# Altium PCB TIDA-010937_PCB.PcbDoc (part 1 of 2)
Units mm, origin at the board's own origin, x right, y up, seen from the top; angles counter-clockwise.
Board outline 43.5 x 86.34 mm, 4 copper layers (Top Layer, GND, PWR, Bottom Layer), stack 1.856 mm thick; 90 components, 44 nets, 203 pads, 101 vias.
Unrouted connection lines stored in the file: 1.
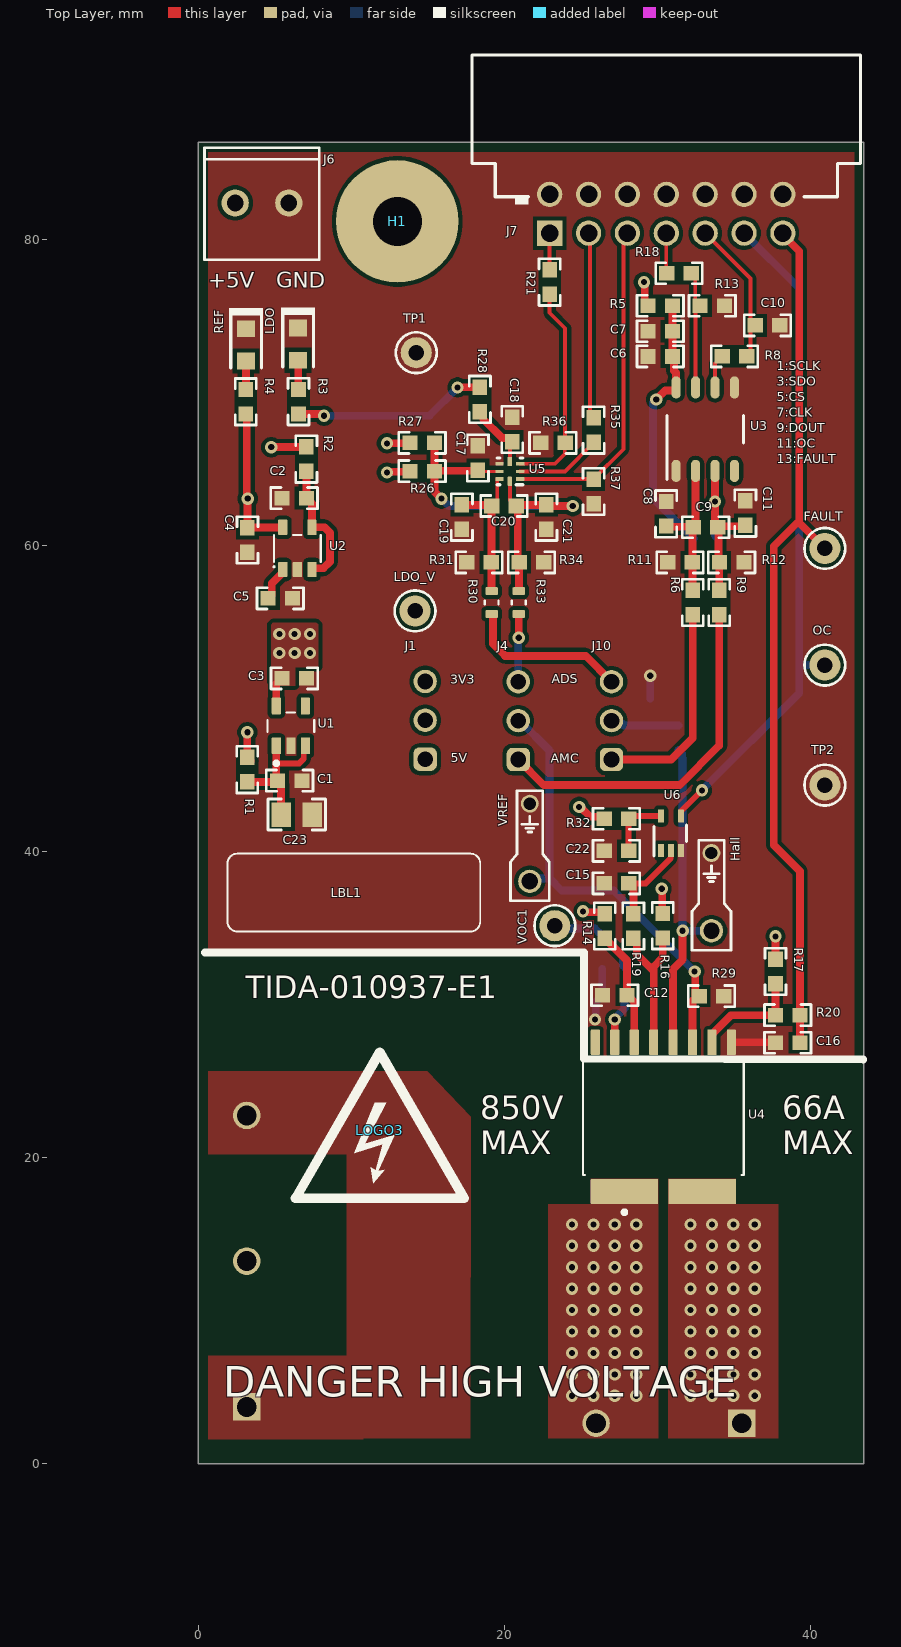
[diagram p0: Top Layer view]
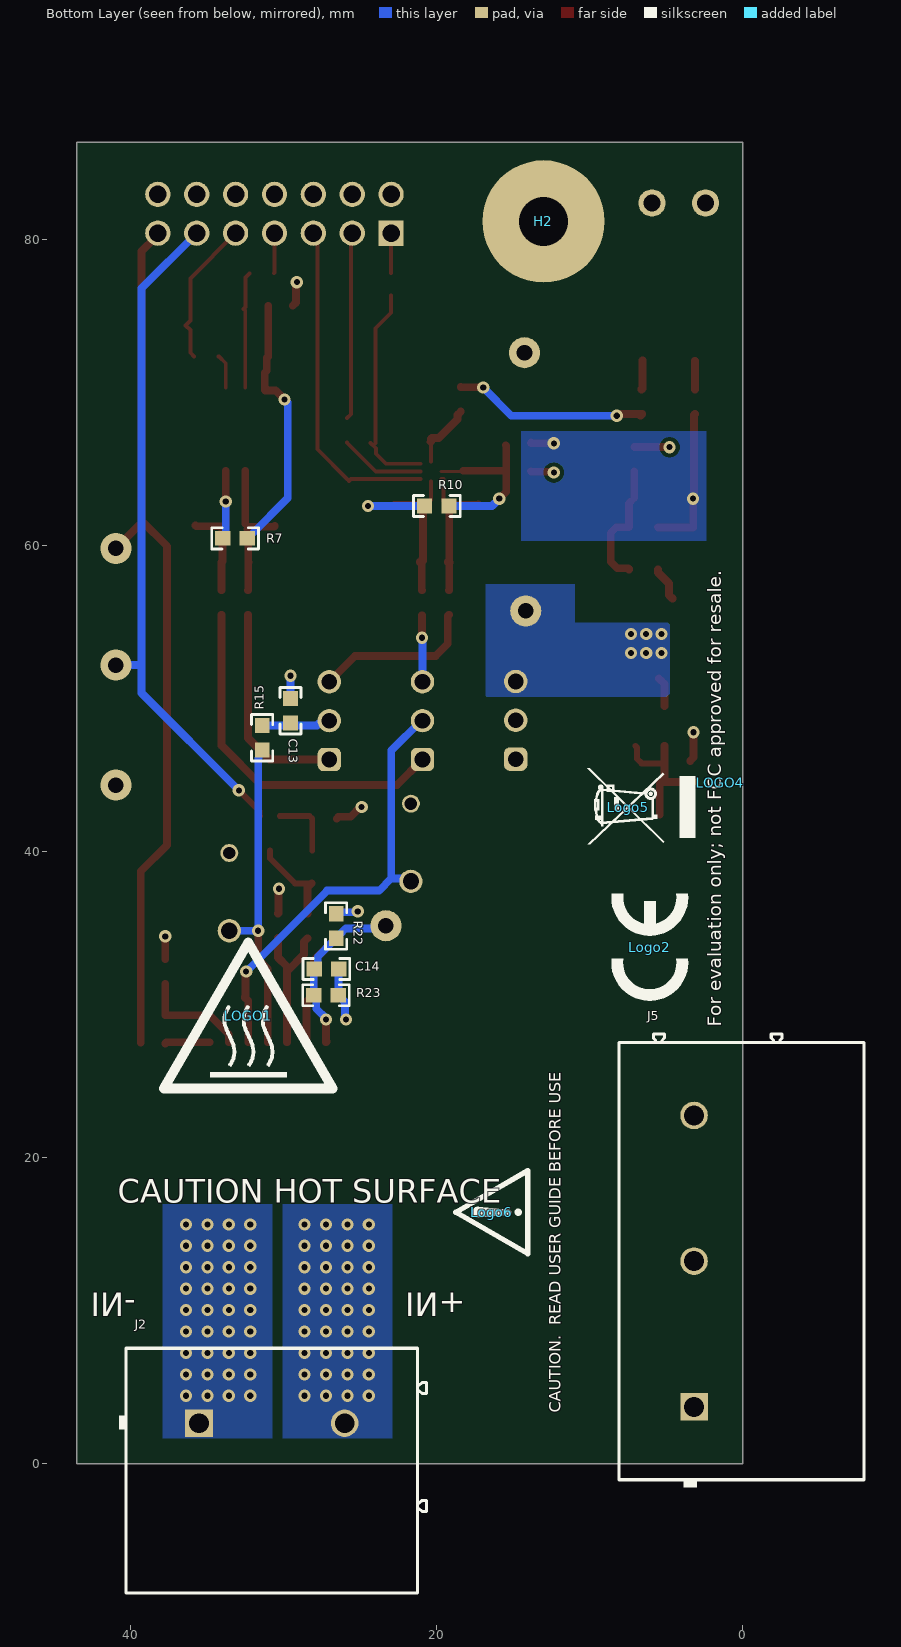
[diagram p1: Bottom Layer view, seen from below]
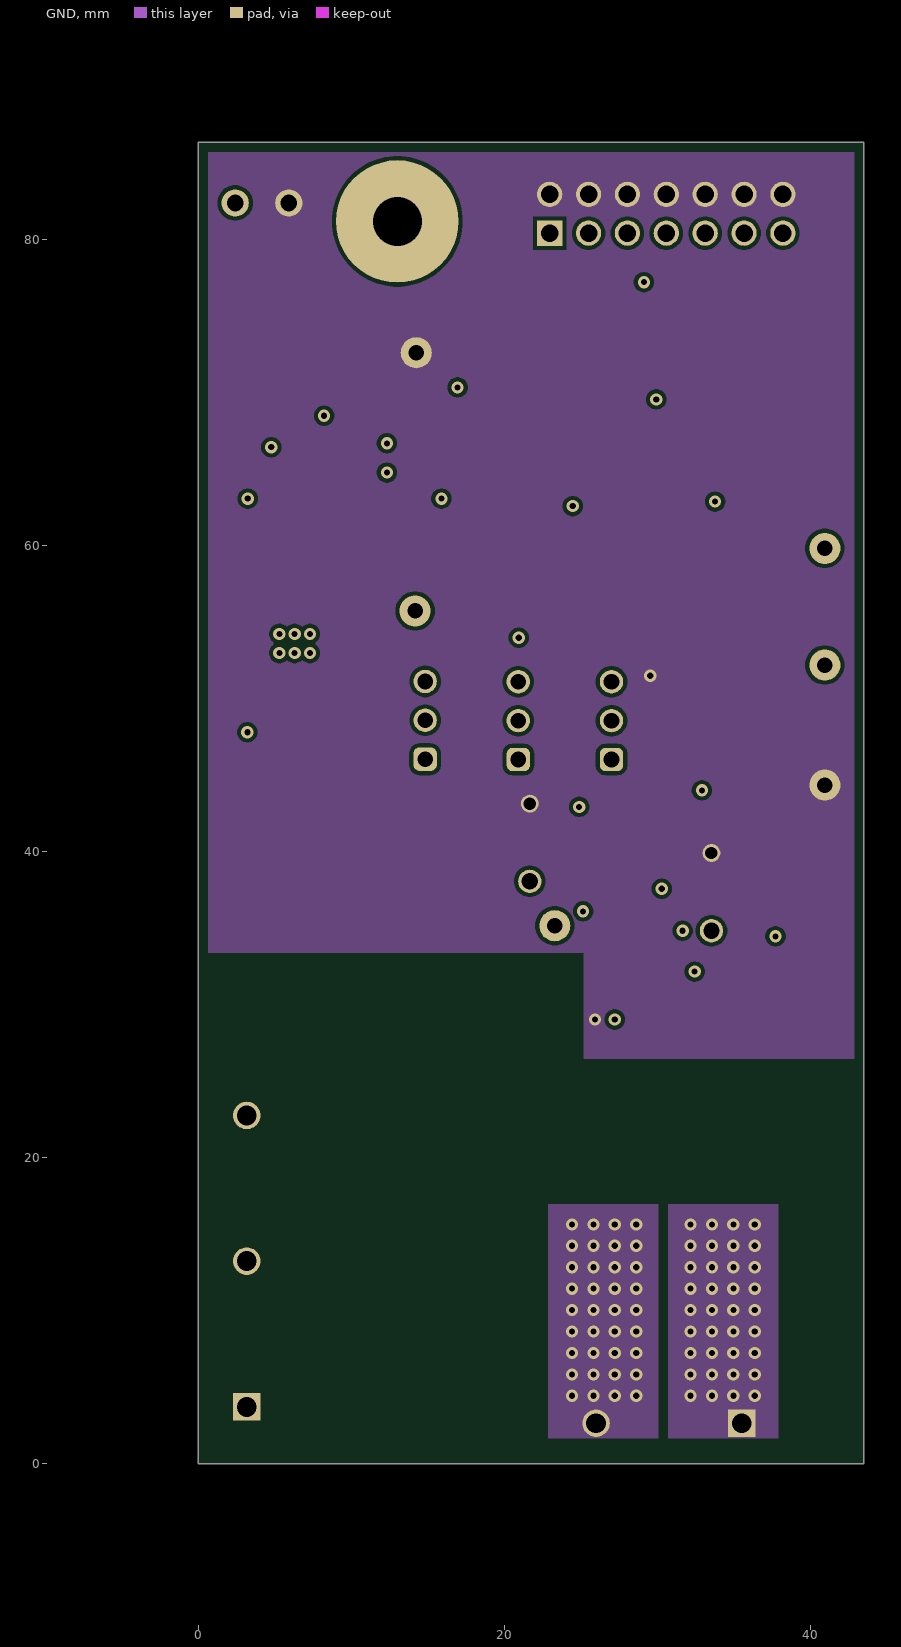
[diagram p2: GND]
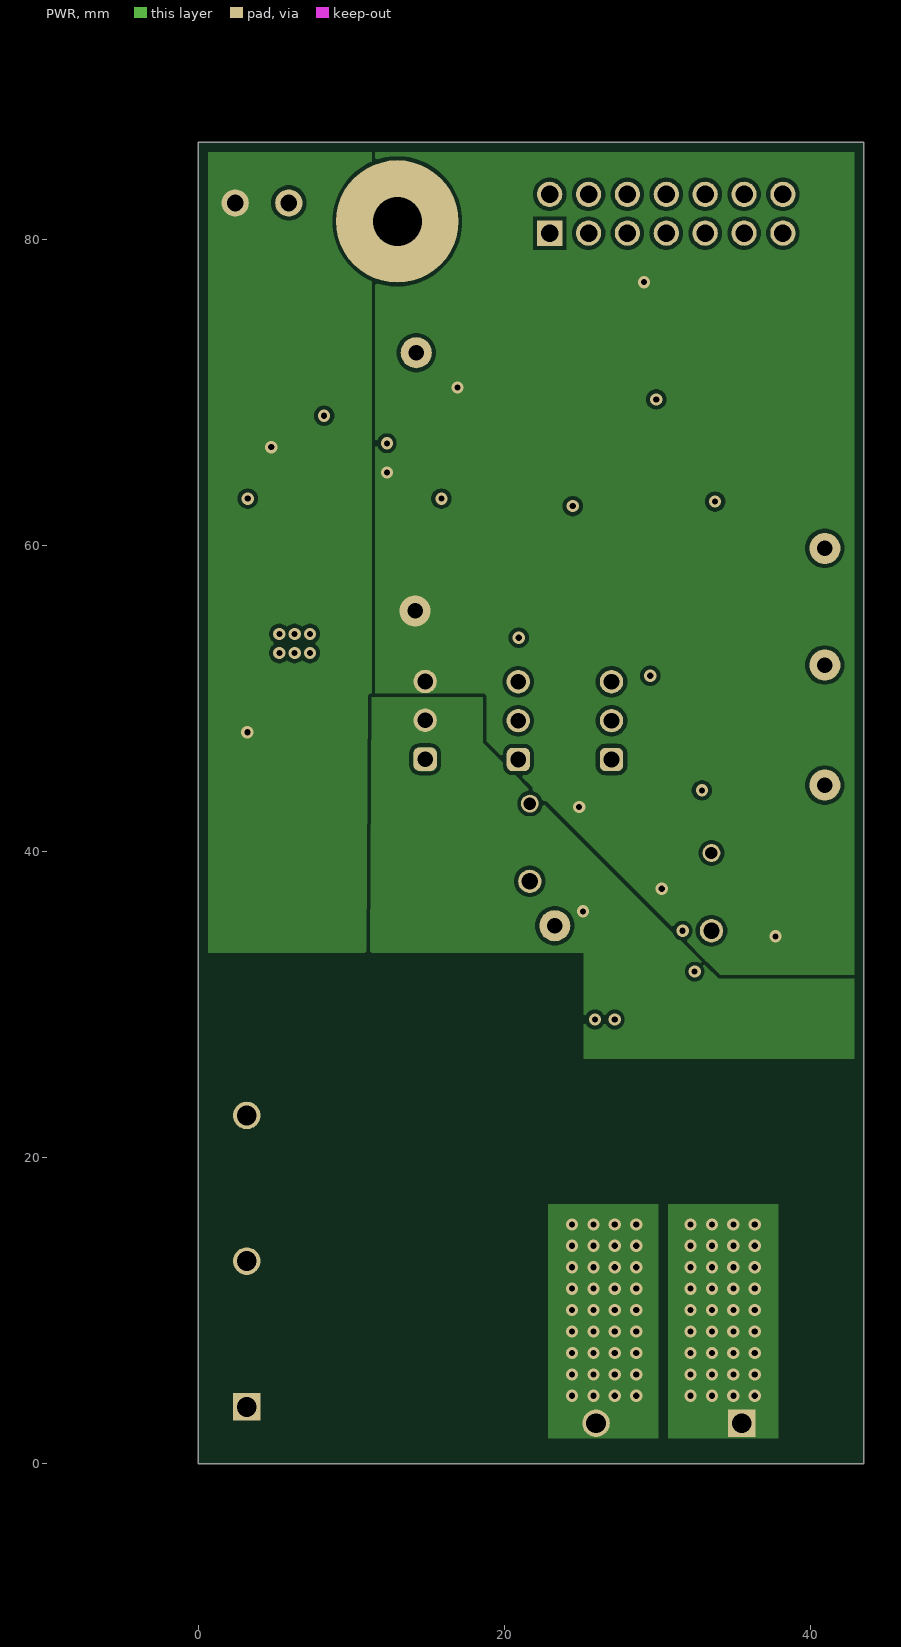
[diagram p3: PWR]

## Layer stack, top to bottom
Top Solder: solder mask 0.0102, Solder Resist, Dk 3.5
Top Layer: signal copper 0.07
Dielectric 1: prepreg 0.0711, PP-006, Dk 4.1
GND: signal copper 0.035
Dielectric1: core 1.5037, FR-4 High Tg, Dk 4.8
PWR: signal copper 0.035
Dielectric 2: prepreg 0.0711, PP-006, Dk 4.1
Bottom Layer: signal copper 0.07
Bottom Solder: solder mask 0.0102, Solder Resist, Dk 3.5

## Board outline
0,0 43.5,0 43.5,86.341 0,86.341

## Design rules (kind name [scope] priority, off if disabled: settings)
AcuteAngle [All] p1: minimum=4.50000000000000E+0001 checktracksonly=FALSE
AssemblyTestPointUsage [All] p1: valid=2
BoardOutlineClearance BoardOutlineClearance_MountingHoles [OnCopper and InComponentClass('Mounting Holes')] p1: gap=1 ignorepadtopadclearanceinfootprint=FALSE
BoardOutlineClearance BoardOutlineClearance_Poly [OnCopper and IsPoly] p2: gap=0.635 ignorepadtopadclearanceinfootprint=FALSE
BoardOutlineClearance [OnCopper and Not InComponentClass('Logo') and not InComponentClass('FiducialMark') and not InRegion(1000,500,4000,800) and not InPoly] p3: gap=1.016 ignorepadtopadclearanceinfootprint=FALSE
Clearance Clearance_Keepouts [((IsTrack Or IsArc) And Not InPoly) And IsFree and IsKeepOut vs ((IsTrack Or IsArc) And Not InPoly) And IsFree and IsKeepOut] p1: gap=0 ignorepadtopadclearanceinfootprint=FALSE
Clearance Clearance_Poly [InPolygon] p2: gap=0.254 ignorepadtopadclearanceinfootprint=TRUE
Clearance Clearance_FiducialMark [IsKeepOut and InComponentClass('FiducialMark') vs IsPad and InComponentClass('FiducialMark')] p3: gap=0 ignorepadtopadclearanceinfootprint=FALSE
Clearance [All] p4: gap=0.2 ignorepadtopadclearanceinfootprint=TRUE except(0: Arc-Arc Arc-Track Track-Track)
ComponentClearance ComponentClearance_MountingHoles_FiducialMarks [InComponentClass('Mounting Holes') vs InComponentClass('FiducialMark')] p1 off: gap=1.27 collisioncheckmode=3 verticalgap=0.254 showdistances=FALSE
ComponentClearance ComponentClearance_Shunt [InComponentClass('Header') vs InComponentClass('Shunt')] p2 off: gap=0 collisioncheckmode=3 verticalgap=0 showdistances=FALSE
ComponentClearance ComponentClearance_Logo [InComponentClass('Logo')] p3 off: gap=0 collisioncheckmode=3 verticalgap=0.254 showdistances=FALSE
ComponentClearance ComponentClearance_ScrewToNut [(HasFootprint('NY PMS 440 0025 PH')) vs (HasFootprint('Keystone_1902C'))] p4 off: gap=0.127 collisioncheckmode=3 verticalgap=0.254 showdistances=FALSE
ComponentClearance ComponentClearance_MountingHoles [InComponentClass('Mounting Holes')] p5 off: gap=2.54 collisioncheckmode=3 verticalgap=2540 showdistances=FALSE
ComponentClearance ComponentClearance_SmallPassives [HasFootprint('0201*') or HasFootprint('0402*') or HasFootprint('0508') or HasFootprint('0603*') or HasFootprint('0612') or HasFootprint('0805*') or HasFootprint('0815*') or HasFootprint('0830*') or HasFootprint('1206*') or HasFootprint('1210*') or HasFootprint('1808*') or HasFootprint('1812*') or HasFootprint('1825*') or HasFootprint('2010*') or HasFootprint('2220*') or HasFootprint('2225*') or HasFootprint('2512*') or HasFootprint('2728*') or HasFootprint('3518*') vs HasFootprint('0201*') or HasFootprint('0402*') or HasFootprint('0508') or HasFootprint('0603*') or HasFootprint('0612') or HasFootprint('0805*') or HasFootprint('0815*') or HasFootprint('0830*') or HasFootprint('1206*') or HasFootprint('1210*') or HasFootprint('1808*') or HasFootprint('1812*') or HasFootprint('1825*') or HasFootprint('2010*') or HasFootprint('2220*') or HasFootprint('2225*') or HasFootprint('2512*') or HasFootprint('2728*') or HasFootprint('3518*')] p6 off: gap=0.38 collisioncheckmode=3 verticalgap=0.254 showdistances=FALSE
ComponentClearance ComponentClearance_THtoSMT [IsThruComponent vs IsSMTComponent] p7 off: gap=0 collisioncheckmode=3 verticalgap=0 showdistances=FALSE
ComponentClearance ComponentClearance_THtoTH [IsThruComponent vs IsThruComponent] p8 off: gap=0.508 collisioncheckmode=3 verticalgap=0 showdistances=FALSE
ComponentClearance [All] p9 off: gap=0 collisioncheckmode=3 verticalgap=0 showdistances=FALSE
DiffPairsRouting [All] p1: maxlimit=2.54 minlimit=0.254 mostfreqgap=0.254 toplayer_minwidth=0.381 toplayer_maxwidth=0.381 toplayer_prefwidth=0.381 midlayer1_minwidth=0.381 midlayer1_maxwidth=0.381 midlayer1_prefwidth=0.381 midlayer2_minwidth=0.381 midlayer2_maxwidth=0.381 midlayer2_prefwidth=0.381 bottomlayer_minwidth=0.381 bottomlayer_maxwidth=0.381 bottomlayer_prefwidth=0.381 maxuncoupledlength=25.4
FabricationTestPointUsage TestPointUsage [All] p1: valid=2 allowmultiple=FALSE
FabricationTestpoint Testpoint [All] p1: side=3 testpointundercomponent=TRUE minsize=1.016 maxsize=2.54 preferedsize=1.524 minholesize=0 maxholesize=1.016 preferedholesize=0.813 testpointgrid=0.025 allowsidetop=TRUE allowsidebottom=TRUE usegrid=TRUE gridtolerance=0
FanoutControl Fanout_LCC [IsLCC] p1: bgadir=Out bgaviamode=Centered fanoutstyle=Auto fanoutdirection=Alternating viagrid=0.025 // Fanout_LCC (Default Rule)
FanoutControl Fanout_BGA [IsBGA] p2: bgadir=Out bgaviamode=Centered fanoutstyle=Auto fanoutdirection=Alternating viagrid=0.025 // Fanout_BGA (Default Rule)
FanoutControl Fanout_Default [All] p4: bgadir=Out bgaviamode=Centered fanoutstyle=Auto fanoutdirection=Alternating viagrid=0.025 // Fanout_Default (Default Rule)
FanoutControl Fanout_Small [(CompPinCount < 5)] p5: bgadir=Out bgaviamode=Centered fanoutstyle=Auto fanoutdirection=OutThenIn viagrid=0.025 // Fanout_Small (Default Rule)
HoleSize [All] p1: absolutevalues=TRUE maxlimit=6.375 minlimit=0.152 maxpercent=80.000 minpercent=20.000
MinimumAnnularRing MinimumAnnularRing_ThermalPadVias [IsVia and InAnyComponent] p1: minimumring=0.15
MinimumAnnularRing [All] p2: minimumring=0.152
MinimumSolderMaskSliver MinimumSolderMaskSliver_Logo [InComponentClass('Logo') vs InComponentClass('Logo')] p1: minsoldermaskwidth=0.018
MinimumSolderMaskSliver [All] p2 off: minsoldermaskwidth=0.1
PlaneConnect [All] p1: planeconnectstyle=Relief reliefexpansion=0.254 reliefentries=4 reliefconductorwidth=0.254 reliefairgap=0.254
PolygonConnect [All] p1: connectstyle=Direct reliefconductorwidth=0.254 reliefentries=4 polygonreliefangle="90 Angle" airgapwidth=0.254
RoutingLayers [All] p1: top layer_v5=TRUE mid layer 1_v5=FALSE mid layer 2_v5=FALSE bottom layer_v5=TRUE
RoutingVias ThermalPadVias [IsVia and InAnyComponent] p1: holewidth=0.2 width=0.5 viastyle="Through Hole" minholewidth=0.2 minwidth=0.5 maxholewidth=0.33 maxwidth=0.6
RoutingVias [All] p2: holewidth=0.406 width=0.864 viastyle="Through Hole" minholewidth=0.2 minwidth=0.61 maxholewidth=1.016 maxwidth=1.651
SilkToBoardRegionClearance [Not ((IsComment or IsDesignator) And (Hide <> 'False')) and not InRegion(1000,500,4000,800)] p1:
SilkToSilkClearance SilkToSilkClearance_Pb-FreeLogo [(HasFootprint('Pb-Free_Overlay_Medium') OR HasFootprint('Pb-Free_Overlay_Small')) vs (HasFootprint('Pb-Free_Overlay_Medium') OR HasFootprint('Pb-Free_Overlay_Small'))] p1: silktosilkclearance=0
SilkToSilkClearance [All] p2: silktosilkclearance=0.1
SilkToSolderMaskClearance SilkToComponentPadClearance [(IsPad or IsFill or IsRegion) and InAnycomponent] p1 off: minsilkscreentomaskgap=0.127 clearancetoexposedcopper=TRUE
SilkToSolderMaskClearance "Silk to Solder Mask Opening" [All] p2 off: minsilkscreentomaskgap=0.1 clearancetoexposedcopper=FALSE
SolderMaskExpansion [All] p1: expansion=0.05 istentingtop=FALSE
UnRoutedNet [All] p1: checkbadconnections=TRUE
Width [All] p1: maxlimit=2.54 minlimit=0.127 preferedwidth=0.254 checkconnectedcopper=TRUE
13 further rules are at their usual default settings.

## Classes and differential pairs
component class "Mounting Holes": H1
component class TIDA-010937_SCH: C1 C2 C3 C4 C5 C6 C7 C8 C9 C10 C11 C12 C13 C14 C15 C16 C17 C18 C19 C20 C21 C22 C23 FAULT Hall J1 J2 J4 J5 J6 J7 J10 LDO LDO_V OC R1 R2 R3 R4 R5 R6 R7 R8 R9 R10 R11 R12 R13 R14 R15 R16 R17 R18 R19 R20 R21 R22 R23 R26 R27 R28 R29 R30 R31 R32 R33 R34 R35 R36 R37 REF TP1 TP2 U1 U2 U3 U4 U5 U6 VOC1 VREF
component class Header: J1 J4 J10
component class TIDA-010937_Hardware: H1 H2 LBL1 LOGO1 Logo2 LOGO3 LOGO4 Logo5 Logo6
component class Label: LBL1

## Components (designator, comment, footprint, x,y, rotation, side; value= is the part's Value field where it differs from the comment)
C1 "C0603C104K8RACTU" 0603 5.981,44.63 r0 top value=0.1uF
C2 "C0603C104K8RACTU" 0603 6.276,63.089 r180 top value=0.1uF
C3 "LMK107BJ225KA-T" 0603 6.286,51.308 r0 top value=2.2uF
C4 "C0603C104K8RACTU" 0603 3.223,60.345 r270 top value=0.1uF
C5 "C0603C104K8RACTU" 0603 5.363,56.529 r0 top value=0.1uF
C6 "GRM188R61C225KE15D" 0603 30.193,72.339 r0 top value=2.2uF
C7 "C0603C104K8RACTU" 0603 30.193,73.992 r180 top value=0.1uF
C8 "C0603C680J5GACTU" 0603 30.572,62.06 r270 top value=68pF
C9 "GRM1885C1E751JA01D" 0603 33.158,61.18 r0 top value=750pF
C10 "GRM1885C1H330JA01D" 0603 37.195,74.372 r0 top value=33pF
C11 "C0603C680J5GACTU" 0603 35.751,62.104 r90 top value=68pF
C12 "C0603C104K8RACTU" 0603 27.221,30.606 r180 top value=0.1uF
C13 "0603ZC101KAT2A" 0603 29.541,49.193 r90 bottom value=100pF
C14 "GRM1885C1E681JA01D" 0603 27.196,32.32 r180 bottom value=1000pF
C15 "GRM1885C1E681JA01D" 0603 27.324,37.918 r180 top value=1000pF
C16 "GRM1885C1E681JA01D" 0603 38.523,27.503 r180 top value=1000pF
C17 "C1608X6S1C335K080AC" 0603 18.28,65.709 r270 top value=3.3uF
C18 "EMK107B7105KAHT" 0603 20.524,67.57 r270 top value=1uF
C19 "06035A300JAT2A" 0603 17.235,61.845 r90 top value=30pF
C20 "GRM1885C1H431JA01D" 0603 19.983,62.57 r0 top value=430pF
C21 "06035A300JAT2A" 0603 22.752,61.845 r270 top value=30pF
C22 "C0603C104K8RACTU" 0603 27.324,40.044 r180 top value=0.1uF
C23 "TMK212BBJ106MG-T" 0805_HV 6.438,42.412 r0 top value=10uF
FAULT "5000" Keystone5000 40.947,59.8 r90 top
H1 "NY PMS 440 0025 PH" "NY PMS 440 0025 PH" 13.013,81.163 r0 top
H2 "2204" Keystone_2204 13.013,81.163 r180 bottom
Hall "" TESTPOINT_PIGTAIL 33.539,34.819 r180 top
J1 "TSW-103-08-G-S" Samtec_TSW-103-08-x-S 14.83,48.567 r90 top
J2 "1902547" Phoenix_1902547 30.759,-0.457 r180 bottom
J4 "TSW-103-08-G-S" Samtec_TSW-103-08-x-S 20.919,48.55 r90 top
J5 "1904150" Phoenix_1904150 0.076,13.233 r90 bottom
J6 "1751248" CONN_1751248 4.172,82.368 r180 top
J7 "702471451" Molex_0702471451 30.588,81.667 r90 top
J10 "TSW-103-08-G-S" Samtec_TSW-103-08-x-S 27.007,48.55 r90 top
LBL1 "THT-14-423-10" Label_650x200 10.177,37.316 r0 top
LDO "150080SS75000" WL-SMCW_RED_0805 6.527,73.145 r270 top value=Red
LDO_V "5000" Keystone5000 14.173,55.714 r90 top
LOGO1 "CAUTION HOT SURFACE" IEC_HotSurface_Medium 32.301,29.274 r180 bottom
Logo2 "CE Mark" CE_Mark_5mm 6.068,33.739 r90 bottom
LOGO3 "DANGER HIGH VOLTAGE" IEC_HighVoltage_Medium 11.873,21.793 r0 top
LOGO4 "FCC disclaimer" FCC_disclaimer 1.473,44.487 r90 bottom
Logo5 "WEEE logo" WEEE_Minimum 7.488,42.901 r90 bottom
Logo6 "CAUTION.  READ USER GUIDE BEFORE USE" IEC_Caution_Small 16.394,16.434 r90 bottom
OC "5000" Keystone5000 40.947,52.18 r90 top
R1 "RC0603JR-070RL" 0603 3.205,45.351 r270 top value=0
R2 "RC0603JR-070RL" 0603 7.076,65.636 r270 top value=0
R3 "RC0603JR-07680RL" 0603 6.558,69.385 r270 top value=680
R4 "RC0603JR-07680RL" 0603 3.11,69.384 r270 top value=680
R5 "RC0603JR-070RL" 0603 30.193,75.655 r0 top value=0
R6 "RT0603BRD071K13L" 0603 32.319,56.264 r90 top value=1.13k
R7 "CPF0603B1K62E" 0603 33.158,60.455 r180 bottom value=1.62k
R8 "CRCW060350R0FKEA" 0603 35.046,72.35 r0 top value=50
R9 "RT0603BRD071K13L" 0603 34.049,56.264 r90 top value=1.13k
R10 "RG1608P-2371-B-T5" 0603 19.983,62.57 r180 bottom value=2.37k
R11 "RT0603BRD07649RL" 0603 31.486,58.89 r0 top value=649
R12 "RT0603BRD07649RL" 0603 34.859,58.89 r180 top value=649
R13 "CRCW0603100KJNEA" 0603 33.589,75.655 r180 top value=100k
R14 "RC0603JR-070RL" 0603 26.567,35.13 r90 top value=0
R15 "RC0603JR-070RL" 0603 31.391,47.427 r90 bottom value=0
R16 "M55342K12B10E0T" 0603 30.354,35.148 r90 top value=10.0k
R17 "M55342K12B10E0T" 0603 37.723,32.156 r90 top value=10.0k
R18 "RC0603JR-070RL" 0603 31.42,77.779 r180 top value=0
R19 "RC0603FR-0710RL" 0603 28.439,35.13 r90 top value=1.00k
R20 "RC0603FR-0710RL" 0603 38.523,29.306 r0 top value=1.00k
R21 "RC0603JR-070RL" 0603 22.968,77.197 r90 top value=0
R22 "RC0603FR-0711K8L" 0603 26.567,35.13 r270 bottom value=11.8k
R23 "RC0603FR-077K87L" 0603 27.221,30.606 r180 bottom value=7.87k
R26 "RC0603JR-070RL" 0603 14.639,64.845 r0 top value=0
R27 "RC0603JR-070RL" 0603 14.639,66.689 r0 top value=0
R28 "RC0603JR-070RL" 0603 18.413,69.537 r90 top value=0
R29 "MCT06030C1004FP500" 0603 33.539,30.549 r180 top value=1.00Meg
R30 "ESR03EZPF10R0" FP-ESR03EZPF10R0_0603-MFG 19.179,56.264 r270 top value=10
R31 "RT0603BRD071K18L" 0603 18.348,58.889 r0 top value=1.18k
R32 "RC0603JR-070RL" 0603 27.324,42.14 r180 top value=0
R33 "ESR03EZPF10R0" FP-ESR03EZPF10R0_0603-MFG 20.948,56.264 r270 top value=10
R34 "RT0603BRD071K18L" 0603 21.78,58.89 r180 top value=1.18k
R35 "RC0603FR-0733RL" 0603 25.84,67.53 r270 top value=33.0
R36 "CRCW0603100KJNEA" 0603 23.177,66.689 r0 top value=100k
R37 "CRCW0603100KJNEA" 0603 25.84,63.515 r90 top value=100k
REF "150080SS75000" WL-SMCW_RED_0805 3.131,73.104 r270 top value=Red
TP1 "5000" Keystone5000 14.252,72.586 r90 top
TP2 "5000" Keystone5000 40.947,44.338 r90 top
U1 "TLV74033PDBVR" DBV0005A-MFG 6.059,48.206 r90 top
U2 "REF2033AIDDCR" DDC0005A_N 6.481,59.802 r90 top
U3 "AMC1035D" D0008A_N 33.135,67.589 r90 top
U4 "TMCS1123B3QDVGR" DVG0010A-MFG 30.396,22.659 r90 top
U5 "ADS7043IRUGR" RUG0008A 20.365,64.834 r180 top
U6 "SN74LVC1G17DCKT" DCK0005A_N 30.891,41.187 r90 top
VOC1 "5000" Keystone5000 23.304,35.148 r0 top
VREF "" TESTPOINT_PIGTAIL 21.673,38.045 r180 top

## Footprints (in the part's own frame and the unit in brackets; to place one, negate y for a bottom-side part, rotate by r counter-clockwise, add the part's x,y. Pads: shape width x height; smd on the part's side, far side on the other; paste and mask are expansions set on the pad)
0603 [mm] "0603 from SM-752 data"
  rect 1x0.95 smd: 1(-0.8,0) 2(0.8,0)
  silkscreen extent -1.52,-0.69 1.52,0.69, body extent -0.87,-0.47 0.87,0.47, height 1
0805_HV [mil] "0805 with 30mil clearance between pads"
  rect 50x63 smd: 1(-40,0) 2(40,0)
  silkscreen extent -74,-40 74,40, body extent -43,-29 43,29, height 57
CE_Mark_5mm [mm] "Minimum text height for CE Mark"
  silkscreen extent -3.5,-2.5 3.5,2.5
CONN_1751248 [mm] "Phoenix Contact"
  round 1.778 hole 1.1: 1(-1.75,0) 2(1.75,0)
  silkscreen extent -3.75,-3.6 3.75,3.7, body extent -3.75,-3.6 3.75,3.7, height 8.52
D0008A_N [mm] "SOIC, 8-Leads, Body 4.9x3.9mm, Pitch 1.27mm, IPC Medium Density"
  oval 1.45x0.6 smd: 1(-2.725,1.905) 2(-2.725,0.635) 3(-2.725,-0.635) 4(-2.725,-1.905) 5(2.725,-1.905) 6(2.725,-0.635) 7(2.725,0.635) 8(2.725,1.905)
  silkscreen extent -3.3,-2.5 0.9,2.5, body extent -3,-2.45 3,2.45, height 1.63
DBV0005A-MFG [mm]
  rrect17% 1.1x0.6 smd paste+0 mask+0: 1(-1.3,0.95) 2(-1.3,0) 3(-1.3,-0.95) 4(1.3,-0.95) 5(1.3,0.95)
  silkscreen extent -2.57,-1.53 0.87,1.53, body extent -1.95,-1.78 1.95,1.78, height 0.25
DCK0005A_N [mm] "SOT353, 5-Leads, Body 2x1.3mm, Pitch 0.65mm, Lead Span 2.1mm, IPC Medium Density"
  rrect25% 0.85x0.4 smd: 1(-1.125,0.65) 2(-1.125,0) 3(-1.125,-0.65) 4(1.125,-0.65) 5(1.125,0.65)
  silkscreen extent -1.48,-1.02 0.55,1.1, body extent -1.14,-1 1.14,1, height 0.95
DDC0005A_N [mm]
  rrect17% 1x0.6 smd: 1(-1.375,0.95) 2(-1.375,0) 3(-1.375,-0.95) 4(1.375,-0.95) 5(1.375,0.95)
  silkscreen extent -1.25,-1.52 0.88,1.57, body extent -1.41,-1.45 1.41,1.45, height 1.1
DVG0010A-MFG [mm]
  rrect6% 1.65x4.41 smd paste+0 mask+0: 1(-4.875,2.54) 2(-4.875,-2.54)
  rrect17% 1.65x0.6 smd paste+0 mask+0: 3(4.875,-4.445) 4(4.875,-3.175) 5(4.875,-1.905) 6(4.875,-0.635) 7(4.875,0.635) 8(4.875,1.905) 9(4.875,3.175) 10(4.875,4.445)
  silkscreen extent -6.35,-5.25 3.8,5.25, body extent -5.15,-5.15 5.15,5.15, height 2.65
FCC_disclaimer [mm]
FP-ESR03EZPF10R0_0603-MFG [mm]
  rrect20% 0.5x0.8 smd paste+0 mask+0: 1(-0.75,0) 2(0.75,0)
  silkscreen extent -0.13,-0.45 0.13,0.45, body extent -1.1,-0.55 1.1,0.55, height 0.25
IEC_Caution_Small [mm]
  silkscreen extent -2.72,-2.36 2.72,2.35
IEC_HighVoltage_Medium [mm]
  silkscreen extent -5.51,-4.46 5.51,5.09
IEC_HotSurface_Medium [mm]
  silkscreen extent -5.51,-4.76 5.51,4.78
Keystone5000 [mil] "For Keystone 500x miniature loop terminals"
  round 80 hole 40: 1(0,0)
  silkscreen extent -52,-52 52,52, body extent -49,-49 49,49, height 182
Keystone_2204 [mm] "HEX STANDOFF 4-40 ALUMINUM 3/4\""
  body extent -3.67,-3.17 3.67,3.18, height 19.05
Label_650x200 [mil] "Thermal Transfer Label"
  round 1 on Mech13: 0(0,0)
  silkscreen extent -325,-100 325,100, body extent -325,-100 325,100, height 1
Molex_0702471451 [mm] "Header(shrouded), 2.54mm, 7x2, R/A, TH"
  rect 1.65x1.65 hole 1.14: 1(-1.27,7.62)
  round 1.65 hole 1.14: 2(1.27,7.62) 3(-1.27,5.08) 4(1.27,5.08) 5(-1.27,2.54) 6(1.27,2.54) 7(-1.27,0) 8(1.27,0) 9(-1.27,-2.54) 10(1.27,-2.54) 11(-1.27,-5.08) 12(1.27,-5.08) 13(-1.27,-7.62) 14(1.27,-7.62)
  silkscreen extent 0.6,-12.7 10.38,12.7, body extent -1.65,-12.7 10.48,12.7, height 8.89
"NY PMS 440 0025 PH" [mm] "4-40 nylon screw and mounting hole"
  round 8 hole 3.2: 1(0,0)
  body extent -3.3,-3.3 3.3,3.3, height 2.69
Phoenix_1902547 [mm] "TH, 2-Leads, Body 19.04x16mm, Pitch 9.52mm"
  rect 1.8x1.8 hole 1.3: 1(-4.76,3.1)
  round 1.8 hole 1.3: 2(4.76,3.1)
  silkscreen extent -10,-8 10.09,8, body extent -9.52,-8 10.09,8, height 22
Phoenix_1904150 [mm] "TH, 3-Leads, Body 28.56x16mm, Pitch 9.52mm"
  rect 1.8x1.8 hole 1.3: 1(-9.52,3.1)
  round 1.8 hole 1.3: 2(0,3.1) 3(9.52,3.1)
  silkscreen extent -14.8,-8 14.85,8, body extent -14.28,-8 14.85,8, height 22
RUG0008A [mm] "QFN, 8-Leads, Body 1.5x1.5mm, Pitch 0.5mm, TI Recommended"
  rrect40% 0.55x0.25 smd: 1(-0.675,0.5) 3(-0.675,-0.5) 5(0.675,-0.5) 7(0.675,0.5)
  rrect50% 0.55x0.2 smd: 2(-0.675,0) 6(0.675,0)
  rrect33% 0.3x0.6 smd: 4(0,-0.65) 8(0,0.65)
  silkscreen extent -0.85,-0.87 0.85,0.87, body extent -0.75,-0.75 0.75,0.75, height 0.4
Samtec_TSW-103-08-x-S [mm] "Header, 2.54mm, 3x1, TH"
  rrect50% 1.53x1.53 hole 1.02: 1(-2.54,0)
  round 1.53 hole 1.02: 2(0,0) 3(2.54,0)
  body extent -3.94,-1.27 3.81,1.27, height 8.38
TESTPOINT_PIGTAIL [mil] "Pigtail"
  round 60 hole 42: 1(0,0)
  round 46 hole 32: 2(0,-200)
  silkscreen extent -50,-233 50,50
WEEE_Minimum [mm] "WEEElie bin"
  silkscreen extent -2.42,-4.38 2.52,2.65
WL-SMCW_RED_0805 [mm] "SMD, 2-Leads, Body 1.6x0.8mm"
  rect 1.1x1.2 smd: 1(-1.05,0) 2(1.05,0)
  silkscreen extent -2.4,-1.1 1.5,1.1, body extent -1,-0.62 1,0.63, height 0.7

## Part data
C1 C2 C4 C5 C7 C12 C22: library part CMP-0006862-3, "CAP, CERM, 0.1 uF, 10 V, +/- 10%, X7R, 0603", Cap_Case=0603, Manufacturer=Kemet, Supplier Part Number 1=399-1095-1-ND, TempCo=X7R, Tolerance_%=10%, Value1=Unknown, Value2=10V, ValueDisplayed=0.1uF
C3: library part CMP-0007506-5, "CAP, CERM, 2.2 uF, 10 V, +/- 10%, X5R, 0603", Cap_Case=0603, Manufacturer="Taiyo Yuden", Supplier Part Number 1=587-1253-1-ND, TempCo=X5R, Tolerance_%=10%, Value1=Unknown, Value2=10V, ValueDisplayed=2.2uF
C6: library part CMP-0007339-4, "CAP, CERM, 2.2 uF, 16 V, +/- 10%, X5R, 0603", Cap_Case=0603, Manufacturer=MuRata, Supplier Part Number 1=490-3296-1-ND, TempCo=X5R, Tolerance_%=10%, Value1=Unknown, Value2=16V, ValueDisplayed=2.2uF
C8 C11: library part CMP-0006958-4, "CAP, CERM, 68 pF, 50 V, +/- 5%, C0G/NP0, 0603", Cap_Case=0603, Manufacturer=Kemet, Supplier Part Number 1=399-1058-1-ND, TempCo=C0G/NP0, Tolerance_%=5%, Value1=Unknown, Value2=50V, ValueDisplayed=68pF
C9: library part CMP-0007167-4, "CAP, CERM, 750 pF, 25 V, +/- 5%, C0G/NP0, 0603", Cap_Case=0603, Manufacturer=MuRata, Supplier Part Number 1=GRM1885C1E751JA01D-ND, TempCo=C0G/NP0, Tolerance_%=5%, Value1=Unknown, Value2=25V, ValueDisplayed=750pF
C10: library part CMP-0007208-2, "CAP, CERM, 33 pF, 50 V, +/- 5%, C0G/NP0, 0603", Cap_Case=0603, Manufacturer=MuRata, Supplier Part Number 1=490-1415-1-ND, TempCo=C0G/NP0, Tolerance_%=5%, Value1=Unknown, Value2=50V, ValueDisplayed=33pF
C13: library part CMP-0006812-1, "CAP, CERM, 100 pF, 10 V, +/- 10%, X7R, 0603", Cap_Case=0603, Manufacturer=AVX, Supplier Part Number 1=0603ZC101KAT2A-ND, TempCo=X7R, Tolerance_%=10%, Value1=Unknown, Value2=10V, ValueDisplayed=100pF
C14 C15 C16: library part CMP-0080092-1, "CAP, CERM, 1000 pF, 25 V,+/- 1%, C0G/NP0, 0603", Cap_Case=0603, Manufacturer=Kemet, PartNumber=C0603C102F3GACTU, Supplier Part Number 1=399-7825-1-ND, TempCo=C0G/NP0, Tolerance_%=1%, Value2=25V, ValueDisplayed=1000pF
C17: library part CMP-0007027-4, "CAP, CERM, 3.3 uF, 16 V, +/- 10%, X6S, 0603", Cap_Case=0603, Manufacturer=TDK, Supplier Part Number 1=445-9096-1-ND, TempCo=X6S, Tolerance_%=10%, Value1="0.004796 ohm", Value2=16V, ValueDisplayed=3.3uF
C18: library part CMP-0080104-1, "CAP, CERM, 1 µF, 16 V,+/- 10%, X7R, AEC-Q200 Grade 1, 0603", Cap_Case=0603, Manufacturer="Taiyo Yuden", Supplier Part Number 1=587-3305-1-ND, TempCo=X7R, Tolerance_%=10%, Value2=16V, ValueDisplayed=1µF
C19 C21: library part CMP-0006782-2, "CAP, CERM, 30 pF, 50 V, +/- 5%, C0G/NP0, 0603", Cap_Case=0603, Manufacturer=AVX, Supplier Part Number 1=478-7917-1-ND, TempCo=C0G/NP0, Tolerance_%=5%, Value1="0.232 ohm", Value2=50V, ValueDisplayed=30pF
C20: library part CMP-0007218-3, "CAP, CERM, 430 pF, 50 V, +/- 5%, C0G/NP0, 0603", Cap_Case=0603, Manufacturer=MuRata, Supplier Part Number 1=490-1442-1-ND, TempCo=C0G/NP0, Tolerance_%=5%, Value1=Unknown, Value2=50V, ValueDisplayed=430pF
C23: library part CMP-0008415-2, "CAP, CERM, 10 uF, 25 V, +/- 20%, X5R, 0805", Cap_Case=0805, Manufacturer="Taiyo Yuden", TempCo=X5R, Tolerance_%=20%, Value1=Unknown, Value2=25V, ValueDisplayed=10uF
FAULT LDO_V OC TP1 TP2 VOC1: library part CMP-0055137-1, "Test Point, Miniature, Red, TH", Color=Red, Manufacturer=Keystone, Supplier Part Number 1=36-5000-ND
H1: library part CMP-0003617-1, "Machine Screw, Round, #4-40 x 1/4, Nylon, Philips panhead", Manufacturer="B&F Fastener Supply", Supplier Part Number 1=H542-ND
H2: library part CMP-0003917-1, Manufacturer=Keystone, Supplier Part Number 1=36-2204-ND
Hall VREF: library part CMP-0003907-1, "PIGTAIL", Manufacturer="Texas Instruments", PartNumber=TESTPOINT_PIGTAIL
J1 J4 J10: library part CMP-0079327-1, "Header, 2.54mm, 3x1, Gold, TH", Color=Black, Manufacturer=Samtec, Supplier Part Number 1=SAM1038-03-ND
J2: library part CMP-0055527-1, "Terminal Block, 9.52mm, 2x1, R/A, TH", Color=Green, Current_A=32A, Manufacturer="Phoenix Contact", Supplier Part Number 1=277-5951-ND, Voltage_V=1kV
J5: library part CMP-0055528-1, "Terminal Block, 9.52mm, 3x1, R/A, TH", Color=Green, Current_A=32A, Manufacturer="Phoenix Contact", Supplier Part Number 1=277-6184-ND, Voltage_V=1kV
J6: library part CMP-0055473-1, "Conn Term Block, 2POS, 3.5mm, TH", Manufacturer="Phoenix Contact", Supplier Part Number 1=277-5719-ND
J7: library part CMP-0055272-2, "Header(shrouded), 2.54mm, 7x2, R/A, Gold, TH", Color=Black, Current_A=2.5A, Manufacturer=Molex, Voltage_V=250V
LBL1: library part CMP-0003625-1, "Thermal Transfer Printable Labels, 0.650\" W x 0.200\" H - 10,000 per roll", Manufacturer=Brady, Supplier Part Number 1=97C5133
LDO REF: library part CMP-0002951-3, "LED, Red, SMD", Color=Red, Manufacturer="Wurth Elektronik", Power_TotalModule=72mW, Value1=0.072W, Value2=1.9V
LOGO1: library part CMP-0074837-1, "IEC 61010-1 Hot Surface Warning"
Logo2: library part CMP-0074844-1
LOGO3: library part CMP-0074835-1, "IEC 61010-1 High Voltage Warning"
LOGO4: library part CMP-0074847-1, "FCC_disclaimer"
Logo5: library part CMP-0074769-1
Logo6: library part CMP-0074836-1, "IEC 61010-1 Caution Warning"
R1 R2 R5 R14 R15 R18 R21 R26 R27 R28 R32: library part CMP-0025885-5, "RES, 0, 5%, 0.1 W, 0603", Manufacturer=Yageo, Power_W=100mW, Supplier Part Number 1=311-0.0GRCT-ND, TempCo="200 ppm/C", Tolerance_%=5%, Value2=0.1W, Value_Code=0000, ValueDisplayed=0
R3 R4: library part CMP-0025936-5, "RES, 680, 5%, 0.1 W, 0603", Manufacturer=Yageo, Power_W=100mW, Supplier Part Number 1=311-680GRCT-ND, TempCo="100 ppm/C", Tolerance_%=5%, Value2=0.1W, Value_Code=680R, ValueDisplayed=680
R6 R9: library part CMP-0023870-3, "RES, 1.13 k, 0.1%, 0.1 W, 0603", Manufacturer="Yageo America", Power_W=100mW, TempCo="25 ppm/C", Tolerance_%=0.1%, Value2=0.1W, Value_Code=1k13, ValueDisplayed=1.13k
R7: library part CMP-0023347-3, "RES, 1.62 k, 0.1%, 0.063 W, 0603", Manufacturer="TE Connectivity", Power_W=63mW, Supplier Part Number 1=4-1879219-0-ND, TempCo="25 ppm/C", Tolerance_%=0.1%, Value2=0.063W, Value_Code=1k62, ValueDisplayed=1.62k
R8: library part CMP-0022479-2, "RES, 50, 1%, 0.1 W, 0603", Manufacturer=Vishay-Dale, Power_W=100mW, Supplier Part Number 1=89M6778, TempCo="100 ppm/C", Tolerance_%=1%, Value2=0.1W, Value_Code=50R0, ValueDisplayed=50
R10: library part CMP-0023481-1, "RES, 2.37 k, 0.1%, 0.1 W, 0603", Manufacturer="Susumu Co Ltd", Power_W=100mW, Supplier Part Number 1=RG16P2.37KBCT-ND, TempCo="25 ppm/C", Tolerance_%=0.1%, Value2=0.1W, Value_Code=2k37, ValueDisplayed=2.37k
R11 R12: library part CMP-0024403-3, "RES, 649, 0.1%, 0.1 W, 0603", Manufacturer="Yageo America", Power_W=100mW, Supplier Part Number 1=YAG1710CT-ND, TempCo="25 ppm/C", Tolerance_%=0.1%, Value2=0.1W, Value_Code=649R, ValueDisplayed=649
R13 R36 R37: library part CMP-0025698-4, "RES, 100 k, 5%, 0.1 W, AEC-Q200 Grade 0, 0603", Manufacturer=Vishay-Dale, Power_W=100mW, Supplier Part Number 1=541-100KGCT-ND, TempCo="200 ppm/C", Tolerance_%=5%, Value2=0.1W, Value_Code=100k
R16 R17: library part CMP-0080488-1, "RES, 10.0 k, 1%, 0.1 W, 0603", Manufacturer="TT Electronics/IRC", Power_W=100mW, TempCo="100 ppm/C", Tolerance_%=1%, Value2=0.1W, Value_Code=10k0, ValueDisplayed=10.0k
R19 R20: library part CMP-0024852-1, "RES, 1.00 k, 0.5%, 0.1 W, 0603", Manufacturer="Yageo America", PartNumber=RT0603DRE071KL, Power_W=100mW, TempCo="50 ppm/C", Tolerance_%=0.5%, Value2=0.1W, Value_Code=1k00, ValueDisplayed=1.00k
R22: library part CMP-0022762-5, "RES, 11.8 k, 1%, 0.1 W, 0603", Manufacturer=Yageo, Power_W=100mW, Supplier Part Number 1=311-11.8KHRCT-ND, TempCo="100 ppm/C", Tolerance_%=1%, Value2=0.1W, Value_Code=11k8, ValueDisplayed=11.8k
R23: library part CMP-0023281-5, "RES, 7.87 k, 1%, 0.1 W, 0603", Manufacturer=Yageo, Power_W=100mW, Supplier Part Number 1=311-7.87KHRCT-ND, TempCo="100 ppm/C", Tolerance_%=1%, Value2=0.1W, Value_Code=7k87, ValueDisplayed=7.87k
R29: library part CMP-0022731-1, "RES, 1.00 M, 1%, 0.125 W, 0603", Manufacturer=Vishay/Beyschlag, Power_W=125mW, Supplier Part Number 1=MCT0603-1.00M-CFCT-ND, TempCo="50 ppm/C", Tolerance_%=1%, Value2=0.125W, Value_Code=1M00, ValueDisplayed=1.00M
R30 R33: library part CMP-0094841-1, "10 Ohms ±1% 0.25W, 1/4W Chip Resistor 0603 (1608 Metric) Automotive AEC-Q200, Pulse Withstanding Thick Film", Digikey Part Number=RHM10.0ADCT-ND, Manufacturer=ROHM, Mouser Part Number=755-ESR03EZPF10R0, Operating Temperature Range="-55°C to +155°C", Power_W=250mW, TempCo=100ppm/°C, Tolerance_%=1%
R31 R34: library part CMP-0023874-3, "RES, 1.18 k, 0.1%, 0.1 W, 0603", Manufacturer="Yageo America", Power_W=100mW, TempCo="25 ppm/C", Tolerance_%=0.1%, Value2=0.1W, Value_Code=1k18, ValueDisplayed=1.18k
R35: library part CMP-0023039-4, "RES, 33.0, 1%, 0.1 W, 0603", Manufacturer=Yageo, Power_W=100mW, Supplier Part Number 1=311-33.0HRCT-ND, TempCo="100 ppm/C", Tolerance_%=1%, Value2=0.1W, Value_Code=33R0, ValueDisplayed=33.0
U1: library part CMP-0090171-1, "300-mA low-dropout (LDO) regulator with foldback current limit 5-SOT-23 -40 to 125", Digikey Part Number=296-TLV74033PDBVRCT-ND, Dropout Voltage=460mV, Manufacturer="Texas Instruments", Max Supply Voltage=5.5V, Mouser Part Number=595-TLV74033PDBVR, Nominal Supply Current=50uA, Operating Temperature Range="-40°C to +125°C", Output Voltage=3.3V
U2: library part CMP-0066190-1, "Low-Drift, Low-Power, Dual-Output VREF and VREF/2 Voltage Reference, DDC0005A (SOT-23-T-5)", Alternate Manufacturer="Texas Instruments", Alternate PartNumber=REF2033AIDDCT
U3: library part CMP-0079285-1, "Delta-Sigma Modulator with Bipolar Input and Reference Output, D0008A (SOIC-8)", Alternate Manufacturer="Texas Instruments", Alternate PartNumber=AMC1035DR
U4: library part CMP-0096053-1, Manufacturer="Texas Instruments", Operating Temperature Range=to
U5: library part CMP-0075943-2, "Ultra-Low Power, Ultra-Small Size, 12-Bit, 1-MSPS, SAR ADC, RUG0008A (X2QFN-8)", Alternate Manufacturer="Texas Instruments"
U6: library part CMP-0051705-3, "Single Schmitt-Trigger Buffer, DCK0005A, SMALL T&R", F @ Nom Voltage(Max)(Mhz)=150, Generic Part Number=SN74LVC1G17, ICC @ Nom Voltage(Max)(mA)=0.01, Manufacturer="Texas Instruments", Operating Temperature Range(C)="-40 to 125,-40 to 85", Rating=Catalog, tpd @ Nom Voltage(Max)(ns)=11,6.5,5.5,5, Voltage(Nom)(V)=1.8,2.5,3.3,5

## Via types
v1: diameter 0.8, hole 0.4, Top Layer to Bottom Layer, 101 vias

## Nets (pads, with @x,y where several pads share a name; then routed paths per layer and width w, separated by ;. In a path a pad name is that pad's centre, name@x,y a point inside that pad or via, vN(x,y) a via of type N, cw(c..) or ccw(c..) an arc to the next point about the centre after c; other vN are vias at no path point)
+5V: J1.1 J6.2 R1.1 R2.1 | length 4.3
  Top Layer w0.508: v1(3.215,47.788) 3.21,47.783 3.21,46.155 R1.1@3.205,46.151 3.426,45.93 R1.1@3.426,45.905 ; v1(4.773,66.414) 4.785,66.425 7.065,66.425 R2.1@7.076,66.436
ADS7043: J10.3 R30.2 | length 10.7
  Top Layer w0.508: R30.2@19.179,55.464 19.264,55.379 19.264,53.569 20.056,52.777 25.321,52.777 J10.3@27.007,51.09
AMC1035: J10.1 R6.1 | length 13.9
  Top Layer w0.508: J10.1@27.007,46.01 30.912,46.01 32.319,47.417 R6.1@32.319,55.464
CLK: R13.2 R18.1 U3.7 | length 7.6
  Top Layer w0.254: R18.1@32.22,77.756 32.476,77.5 32.476,75.572 32.608,75.439 32.5,75.332 32.5,74.058 U3.7@32.5,70.314
CS: J7.5 R37.2 U5.1 | length 21.7
  Top Layer w0.254: U5.1@21.04,64.334 25.601,64.334 R37.2@25.73,64.205 ; R37.2@25.84,64.315 25.84,64.34 27.78,66.281 27.78,80.13 J7.5@28.048,80.397
DOUT: C10.1 J7.9 R8.2 | length 9.6
  Top Layer w0.254: J7.9@33.128,80.397 36.081,77.443 36.081,74.686 C10.1@36.395,74.372 36.081,74.058 36.081,72.586 R8.2@35.846,72.35
FAULT: C16.1 FAULT.1 J7.13 R20.2 | length 56.9
  Top Layer w0.508: J7.13@38.35,80.14 39.273,79.217 39.273,61.599 ; C16.1@39.323,27.503 R20.2@39.323,29.306 39.323,38.709 37.605,40.427 37.605,59.931 39.273,61.599 ; FAULT.1@40.947,59.8 39.273,61.474 39.273,61.599
GND: C1.2 C2.2 C3.2 C4.2 C5.2 C6.1 C7.2 C8.1 C10.2 C11.2 C12.2 C13.2 C14.2 C15.2 C16.2 C17.1 C18.1 C19.1 C21.2 C22.2 C23.2 Hall.2 J6.1 J7.2 J7.4 J7.6 J7.8 J7.10 J7.12 J7.14 LDO.1 R11.1 R12.1 R13.1 R23.2 R29.1 R31.1 R34.1 R36.1 R37.1 REF.1 TP1.1 TP2.1 U1.2 U2.2 U3.1 U3.5 U4.3 U5.5 U6.3 VREF.2 | length 8.1
  Top Layer w0.508: C12.2@26.396,30.606 C12.2@26.421,30.606 ; Hall.2@33.457,39.981 Hall.2@33.539,39.899 ; U4.3@34.841,27.534 37.636,27.534 C16.2@37.723,27.448
  Bottom Layer w0.508: v1(25.923,29.021) 25.979,29.077 25.979,30.164 26.175,30.36 26.175,30.385 R23.2@26.396,30.606 ; C14.2@26.396,32.32 26.409,32.308 26.409,30.618 R23.2@26.396,30.606 ; R23.2@26.421,30.606 R23.2@26.396,30.606 ; C13.2@29.541,49.993 v1(29.541,51.483)
Hall_Vo: C13.1 J10.2 R15.2 | length 4.5
  Bottom Layer w0.508: J10.2@27.007,48.55 27.203,48.354 27.689,48.354 27.816,48.227 29.509,48.227 R15.2@31.391,48.227
IN1: J5.1 J5.3
IN+: J2.2 U4.1
  other v1: 24.423,4.436 25.823,4.436 27.223,4.436 28.623,4.436 24.423,5.836 25.823,5.836 27.223,5.836 28.623,5.836 24.423,7.236 25.823,7.236 27.223,7.236 28.623,7.236 24.423,8.636 25.823,8.636 27.223,8.636 28.623,8.636 24.423,10.036 25.823,10.036 27.223,10.036 28.623,10.036 24.423,11.436 25.823,11.436 27.223,11.436 28.623,11.436 24.423,12.836 25.823,12.836 27.223,12.836 28.623,12.836 24.423,14.236 25.823,14.236 27.223,14.236 28.623,14.236 24.423,15.636 25.823,15.636 27.223,15.636 28.623,15.636
IN-: J2.1 U4.2
  other v1: 32.169,4.436 33.569,4.436 34.969,4.436 36.369,4.436 32.169,5.836 33.569,5.836 34.969,5.836 36.369,5.836 32.169,7.236 33.569,7.236 34.969,7.236 36.369,7.236 32.169,8.636 33.569,8.636 34.969,8.636 36.369,8.636 32.169,10.036 33.569,10.036 34.969,10.036 36.369,10.036 32.169,11.436 33.569,11.436 34.969,11.436 36.369,11.436 32.169,12.836 33.569,12.836 34.969,12.836 36.369,12.836 32.169,14.236 33.569,14.236 34.969,14.236 36.369,14.236 32.169,15.636 33.569,15.636 34.969,15.636 36.369,15.636
LDO_3V3: C3.1 J1.3 LDO_V.1 R3.2 R5.1 R16.2 R17.2 R26.1 R28.2 R32.2 U1.5 | length 23
  Top Layer w0.508: U1.5@5.109,49.506 5.109,50.957 5.285,51.133 5.31,51.133 C3.1@5.486,51.308 ; R3.2@6.674,68.47 R3.2@6.558,68.585 8.033,68.585 8.148,68.47 v1(8.227,68.47) ; v1@12.381,64.802 13.795,64.802 R26.1@13.839,64.845 ; v1(16.951,70.314) 16.963,70.326 18.401,70.326 R28.2@18.413,70.337 ; v1(24.894,42.906) 24.973,42.906 25.613,42.266 26.399,42.266 R32.2@26.524,42.14 ; v1(29.127,77.197) 29.182,77.141 29.182,75.865 R5.1@29.393,75.655 ; v1(30.291,37.568) 30.323,37.536 30.323,35.98 R16.2@30.354,35.948 ; R17.2@37.723,32.956 v1(37.723,34.455)
  Bottom Layer w0.508: v1@8.258,68.47 15.108,68.47 v1(16.951,70.314)
  other v1: 5.307,52.96 6.305,52.96 7.303,52.96 5.307,54.211 6.305,54.211 7.303,54.211 12.337,64.758
NetC1_1: C1.1 C23.1 R1.2 U1.1 U1.3 | length 9.5
  Top Layer w0.381: 5.109,45.881 5.234,45.756 6.601,45.756 6.9,46.055 6.9,46.797 U1.3@7.009,46.906
  Top Layer w0.508: R1.2@3.205,44.551 3.221,44.535 C1.1@5.296,44.535 ; U1.1@5.109,46.906 5.109,45.881 5.109,44.868 C1.1@5.264,44.713 ; C1.1@5.181,44.63 5.201,44.63 C1.1@5.296,44.535 ; C23.1@5.422,42.412 5.422,44.409 C1.1@5.296,44.535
